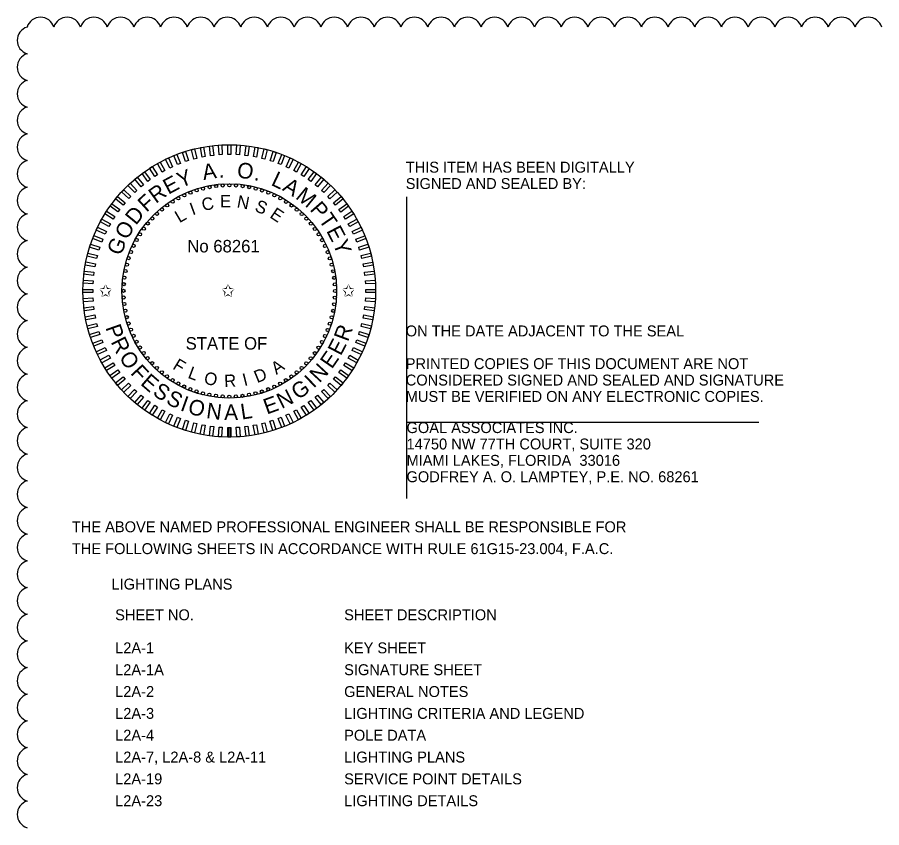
# Model space of a CAD drawing. Extents: x -811 to 10319, y -2309 to 9962.
# Drawn here: x -810.85 to -805.31, y -2194.13 to -2188.94 of the extents above; entities that cross this region are included whole.
import ezdxf

# ---------------------------------------------------------------- set-up
doc = ezdxf.new("R2010")
doc.units = 0
for name, color, linetype in [('AdhocPoint_dp', 7, 'Continuous'), ('PlotBorder_dp', 7, 'Continuous'), ('TextMinor', 7, 'Continuous'), ('TextMisc', 7, 'Continuous'), ('TextShtNo', 7, 'Continuous'), ('TextTitle', 7, 'Continuous')]:
    doc.layers.add(name, color=color, linetype=linetype)

msp = doc.modelspace()

# ---------------------------------------------------------------- linework, layer by layer
at = {"layer": 'AdhocPoint_dp'}
for p, q in [((-808.3546, -2190.0892), (-808.3546, -2192.0239)), ((-808.3546, -2191.5339), (-806.0979, -2191.5339))]:
    msp.add_line(p, q, dxfattribs=at)
at = {"layer": 'TextMinor'}
for radius in [0.9375, 0.6875]:
    msp.add_circle((-809.4901, -2190.6926), radius, dxfattribs=at)
at = {"layer": 'TextShtNo'}
for p, q in [((-809.5001, -2191.6301), (-809.5003, -2191.5676)), ((-809.4901, -2191.6301), (-809.4903, -2191.5676)), ((-809.4801, -2191.6301), (-809.4803, -2191.5676))]:
    msp.add_line(p, q, dxfattribs=at)
for points in [[(-809.5897, -2189.8232), (-809.6097, -2189.8257), (-809.6175, -2189.7638), (-809.5975, -2189.7612)], [(-809.5349, -2189.8187), (-809.555, -2189.8199), (-809.559, -2189.7576), (-809.5388, -2189.7563)], [(-809.4799, -2189.8176), (-809.5001, -2189.8176), (-809.5001, -2189.7551), (-809.4799, -2189.7551)], [(-809.425, -2189.8199), (-809.4452, -2189.8187), (-809.4412, -2189.7563), (-809.4211, -2189.7576)], [(-809.3703, -2189.8257), (-809.3904, -2189.8232), (-809.3825, -2189.7613), (-809.3625, -2189.7638)], [(-809.8028, -2189.8753), (-809.8215, -2189.8827), (-809.8445, -2189.8246), (-809.8258, -2189.8172)], [(-809.7508, -2189.8572), (-809.77, -2189.8635), (-809.7893, -2189.8041), (-809.7701, -2189.7979)], [(-809.6979, -2189.8425), (-809.7174, -2189.8475), (-809.7329, -2189.7871), (-809.7134, -2189.782)], [(-809.6441, -2189.8312), (-809.6639, -2189.8349), (-809.6756, -2189.7736), (-809.6558, -2189.7698)], [(-809.3162, -2189.835), (-809.336, -2189.8312), (-809.3243, -2189.7699), (-809.3045, -2189.7736)], [(-809.2626, -2189.8476), (-809.2822, -2189.8426), (-809.2667, -2189.7821), (-809.2471, -2189.7871)], [(-809.21, -2189.8635), (-809.2292, -2189.8573), (-809.2099, -2189.7979), (-809.1907, -2189.8042)], [(-809.1585, -2189.8828), (-809.1773, -2189.8753), (-809.1543, -2189.8173), (-809.1355, -2189.8247)], [(-809.9027, -2189.9209), (-809.9204, -2189.9306), (-809.9505, -2189.8759), (-809.9328, -2189.8662)], [(-809.8535, -2189.8965), (-809.8717, -2189.9051), (-809.8983, -2189.8486), (-809.8801, -2189.84)], [(-809.1083, -2189.9052), (-809.1266, -2189.8966), (-809.1, -2189.8401), (-809.0817, -2189.8487)], [(-809.0596, -2189.9307), (-809.0773, -2189.921), (-809.0473, -2189.8663), (-809.0296, -2189.876)], [(-809.9962, -2189.9787), (-810.0125, -2189.9906), (-810.0492, -2189.94), (-810.0329, -2189.9282)], [(-809.9504, -2189.9483), (-809.9674, -2189.9591), (-810.0009, -2189.9064), (-809.9838, -2189.8956)], [(-809.0127, -2189.9592), (-809.0297, -2189.9484), (-808.9962, -2189.8957), (-808.9792, -2189.9065)], [(-808.9676, -2189.9907), (-808.9839, -2189.9788), (-808.9472, -2189.9283), (-808.9308, -2189.9402)], [(-810.04, -2190.0119), (-810.0556, -2190.0247), (-810.0954, -2189.9766), (-810.0798, -2189.9638)], [(-808.9245, -2190.0249), (-808.9401, -2190.012), (-808.9003, -2189.9639), (-808.8847, -2189.9768)], [(-810.0817, -2190.0478), (-810.0964, -2190.0616), (-810.1392, -2190.0161), (-810.1244, -2190.0022)], [(-808.8837, -2190.0617), (-808.8984, -2190.0479), (-808.8557, -2190.0024), (-808.841, -2190.0162)], [(-810.1579, -2190.127), (-810.1707, -2190.1425), (-810.2188, -2190.1027), (-810.206, -2190.0872)], [(-810.121, -2190.0862), (-810.1348, -2190.1009), (-810.1804, -2190.0581), (-810.1665, -2190.0434)], [(-808.8453, -2190.101), (-808.8591, -2190.0863), (-808.8136, -2190.0436), (-808.7998, -2190.0583)], [(-808.8094, -2190.1427), (-808.8223, -2190.1271), (-808.7742, -2190.0873), (-808.7613, -2190.1029)], [(-810.192, -2190.17), (-810.2039, -2190.1864), (-810.2544, -2190.1497), (-810.2426, -2190.1333)], [(-808.7762, -2190.1865), (-808.7881, -2190.1702), (-808.7376, -2190.1335), (-808.7257, -2190.1498)], [(-810.2235, -2190.2151), (-810.2343, -2190.2322), (-810.287, -2190.1987), (-810.2762, -2190.1817)], [(-808.7459, -2190.2323), (-808.7567, -2190.2153), (-808.7039, -2190.1818), (-808.6931, -2190.1989)], [(-810.252, -2190.2621), (-810.2617, -2190.2798), (-810.3164, -2190.2497), (-810.3067, -2190.232)], [(-808.7184, -2190.28), (-808.7281, -2190.2623), (-808.6734, -2190.2322), (-808.6637, -2190.2499)], [(-810.2775, -2190.3108), (-810.2861, -2190.3291), (-810.3426, -2190.3025), (-810.334, -2190.2842)], [(-808.694, -2190.3292), (-808.7026, -2190.311), (-808.6461, -2190.2844), (-808.6375, -2190.3027)], [(-810.3, -2190.361), (-810.3074, -2190.3798), (-810.3654, -2190.3568), (-810.358, -2190.338)], [(-808.6728, -2190.3799), (-808.6802, -2190.3612), (-808.6222, -2190.3382), (-808.6147, -2190.357)], [(-810.3192, -2190.4125), (-810.3254, -2190.4317), (-810.3848, -2190.4124), (-810.3786, -2190.3932)], [(-808.6548, -2190.4319), (-808.661, -2190.4127), (-808.6016, -2190.3934), (-808.5954, -2190.4126)], [(-810.3351, -2190.4651), (-810.3401, -2190.4847), (-810.4006, -2190.4691), (-810.3956, -2190.4496)], [(-808.64, -2190.4849), (-808.6451, -2190.4653), (-808.5846, -2190.4498), (-808.5796, -2190.4693)], [(-810.3477, -2190.5186), (-810.3515, -2190.5385), (-810.4129, -2190.5268), (-810.4091, -2190.5069)], [(-808.6287, -2190.5386), (-808.6325, -2190.5188), (-808.5711, -2190.5071), (-808.5673, -2190.5269)], [(-810.357, -2190.5728), (-810.3595, -2190.5928), (-810.4215, -2190.585), (-810.4189, -2190.565)], [(-808.6207, -2190.593), (-808.6232, -2190.573), (-808.5613, -2190.5652), (-808.5588, -2190.5852)], [(-810.3628, -2190.6275), (-810.3641, -2190.6476), (-810.4264, -2190.6437), (-810.4251, -2190.6236)], [(-808.6162, -2190.6478), (-808.6174, -2190.6277), (-808.5551, -2190.6238), (-808.5539, -2190.6439)], [(-810.3652, -2190.6824), (-810.3652, -2190.7026), (-810.4276, -2190.7026), (-810.4276, -2190.6824)], [(-808.6151, -2190.7028), (-808.6151, -2190.6826), (-808.5527, -2190.6826), (-808.5527, -2190.7028)], [(-810.3641, -2190.7374), (-810.3628, -2190.7575), (-810.4251, -2190.7614), (-810.4264, -2190.7413)], [(-808.6175, -2190.7577), (-808.6162, -2190.7376), (-808.5539, -2190.7415), (-808.5551, -2190.7616)], [(-810.3595, -2190.7922), (-810.357, -2190.8122), (-810.4189, -2190.82), (-810.4215, -2190.8)], [(-808.6233, -2190.8124), (-808.6207, -2190.7923), (-808.5588, -2190.8002), (-808.5613, -2190.8202)], [(-810.3516, -2190.8466), (-810.3478, -2190.8664), (-810.4091, -2190.8781), (-810.4129, -2190.8583)], [(-808.6325, -2190.8666), (-808.6287, -2190.8467), (-808.5674, -2190.8584), (-808.5712, -2190.8783)], [(-810.3402, -2190.9003), (-810.3352, -2190.9199), (-810.3957, -2190.9354), (-810.4007, -2190.9159)], [(-808.6451, -2190.9201), (-808.6401, -2190.9005), (-808.5796, -2190.916), (-808.5846, -2190.9356)], [(-810.3255, -2190.9533), (-810.3192, -2190.9725), (-810.3786, -2190.9918), (-810.3849, -2190.9726)], [(-808.6611, -2190.9727), (-808.6548, -2190.9535), (-808.5954, -2190.9728), (-808.6017, -2190.992)], [(-810.3075, -2191.0052), (-810.3, -2191.024), (-810.3581, -2191.047), (-810.3655, -2191.0282)], [(-808.6803, -2191.0242), (-808.6729, -2191.0054), (-808.6148, -2191.0284), (-808.6222, -2191.0472)], [(-810.2862, -2191.0559), (-810.2776, -2191.0742), (-810.3341, -2191.1008), (-810.3427, -2191.0825)], [(-808.7027, -2191.0744), (-808.6941, -2191.0561), (-808.6376, -2191.0827), (-808.6462, -2191.101)], [(-810.2618, -2191.1052), (-810.2521, -2191.1229), (-810.3068, -2191.153), (-810.3165, -2191.1353)], [(-808.7282, -2191.1231), (-808.7185, -2191.1054), (-808.6638, -2191.1355), (-808.6735, -2191.1532)], [(-810.2344, -2191.1529), (-810.2236, -2191.1699), (-810.2763, -2191.2034), (-810.2871, -2191.1863)], [(-810.204, -2191.1987), (-810.1922, -2191.215), (-810.2427, -2191.2517), (-810.2545, -2191.2354)], [(-808.7882, -2191.2152), (-808.7763, -2191.1988), (-808.7258, -2191.2355), (-808.7377, -2191.2519)], [(-808.7568, -2191.1701), (-808.746, -2191.153), (-808.6932, -2191.1865), (-808.704, -2191.2035)], [(-810.1708, -2191.2425), (-810.158, -2191.2581), (-810.2061, -2191.2979), (-810.2189, -2191.2823)], [(-808.8224, -2191.2582), (-808.8095, -2191.2427), (-808.7614, -2191.2825), (-808.7743, -2191.298)], [(-810.135, -2191.2842), (-810.1211, -2191.2989), (-810.1667, -2191.3416), (-810.1805, -2191.3269)], [(-808.8592, -2191.299), (-808.8454, -2191.2843), (-808.7999, -2191.327), (-808.8137, -2191.3418)], [(-810.0965, -2191.3235), (-810.0818, -2191.3373), (-810.1246, -2191.3828), (-810.1393, -2191.369)], [(-810.0557, -2191.3603), (-810.0402, -2191.3732), (-810.08, -2191.4213), (-810.0955, -2191.4084)], [(-808.9402, -2191.3733), (-808.9247, -2191.3604), (-808.8848, -2191.4086), (-808.9004, -2191.4214)], [(-808.8985, -2191.3374), (-808.8838, -2191.3236), (-808.8411, -2191.3691), (-808.8558, -2191.383)], [(-810.0127, -2191.3945), (-809.9964, -2191.4064), (-810.0331, -2191.4569), (-810.0494, -2191.445)], [(-808.984, -2191.4065), (-808.9677, -2191.3946), (-808.931, -2191.4451), (-808.9473, -2191.457)], [(-809.9676, -2191.426), (-809.9505, -2191.4368), (-809.984, -2191.4895), (-810.001, -2191.4787)], [(-809.9206, -2191.4545), (-809.9029, -2191.4642), (-809.933, -2191.5189), (-809.9507, -2191.5092)], [(-809.0775, -2191.4643), (-809.0598, -2191.4546), (-809.0297, -2191.5093), (-809.0474, -2191.519)], [(-809.0299, -2191.4369), (-809.0128, -2191.4261), (-808.9794, -2191.4788), (-808.9964, -2191.4896)], [(-809.8719, -2191.48), (-809.8536, -2191.4886), (-809.8802, -2191.5451), (-809.8985, -2191.5365)], [(-809.8217, -2191.5024), (-809.8029, -2191.5099), (-809.8259, -2191.5679), (-809.8447, -2191.5605)], [(-809.7702, -2191.5217), (-809.751, -2191.5279), (-809.7703, -2191.5873), (-809.7895, -2191.581)], [(-809.2294, -2191.5279), (-809.2102, -2191.5217), (-809.1909, -2191.5811), (-809.2101, -2191.5873)], [(-809.1775, -2191.5099), (-809.1587, -2191.5025), (-809.1357, -2191.5606), (-809.1545, -2191.568)], [(-809.1268, -2191.4887), (-809.1085, -2191.4801), (-809.0819, -2191.5366), (-809.1002, -2191.5452)], [(-809.7176, -2191.5376), (-809.698, -2191.5426), (-809.7136, -2191.6031), (-809.7331, -2191.5981)], [(-809.6641, -2191.5502), (-809.6443, -2191.554), (-809.656, -2191.6153), (-809.6758, -2191.6116)], [(-809.6099, -2191.5594), (-809.5899, -2191.562), (-809.5977, -2191.6239), (-809.6177, -2191.6214)], [(-809.5552, -2191.5653), (-809.5351, -2191.5665), (-809.539, -2191.6288), (-809.5592, -2191.6276)], [(-809.5003, -2191.5676), (-809.4801, -2191.5676), (-809.4801, -2191.6301), (-809.5003, -2191.6301)], [(-809.4453, -2191.5665), (-809.4252, -2191.5653), (-809.4213, -2191.6276), (-809.4414, -2191.6289)], [(-809.3906, -2191.562), (-809.3705, -2191.5595), (-809.3627, -2191.6214), (-809.3827, -2191.624)], [(-809.3362, -2191.554), (-809.3163, -2191.5503), (-809.3046, -2191.6116), (-809.3245, -2191.6154)], [(-809.2824, -2191.5427), (-809.2628, -2191.5376), (-809.2473, -2191.5981), (-809.2668, -2191.6031)]]:
    msp.add_lwpolyline(points, close=True, dxfattribs=at)
for centre in [(-809.6989, -2190.0481), (-809.6581, -2190.0363), (-809.6165, -2190.027), (-809.5745, -2190.0204), (-809.5321, -2190.0164), (-809.4896, -2190.0151), (-809.447, -2190.0165), (-809.4047, -2190.0205), (-809.3626, -2190.0272), (-809.3211, -2190.0366), (-809.2802, -2190.0485), (-809.816, -2190.0987), (-809.7781, -2190.0794), (-809.739, -2190.0625), (-809.2402, -2190.0629), (-809.2012, -2190.0798), (-809.1633, -2190.0992), (-809.8879, -2190.1442), (-809.8527, -2190.1203), (-809.1266, -2190.1209), (-809.0915, -2190.1448), (-809.9535, -2190.1984), (-809.9215, -2190.1702), (-809.0579, -2190.171), (-809.026, -2190.1991), (-810.0118, -2190.2603), (-809.9836, -2190.2284), (-808.9959, -2190.2292), (-808.9678, -2190.2612), (-810.0379, -2190.2939), (-808.9417, -2190.2948), (-810.0835, -2190.3657), (-810.0618, -2190.3291), (-808.9178, -2190.3301), (-808.8962, -2190.3667), (-810.1029, -2190.4036), (-808.8769, -2190.4047), (-810.1343, -2190.4827), (-810.1198, -2190.4427), (-808.86, -2190.4437), (-808.8456, -2190.4838), (-810.1462, -2190.5236), (-808.8338, -2190.5247), (-810.1555, -2190.5651), (-808.8245, -2190.5662), (-810.1662, -2190.6495), (-810.1622, -2190.6071), (-808.8179, -2190.6082), (-808.814, -2190.6506), (-810.1676, -2190.692), (-808.8127, -2190.6932), (-810.1663, -2190.7346), (-808.814, -2190.7357), (-810.1623, -2190.7769), (-810.1557, -2190.819), (-808.8248, -2190.8201), (-808.8181, -2190.7781), (-810.1464, -2190.8605), (-808.8341, -2190.8616), (-810.1346, -2190.9014), (-808.846, -2190.9025), (-810.1202, -2190.9415), (-810.1034, -2190.9805), (-808.8774, -2190.9816), (-808.8604, -2190.9425), (-810.0841, -2191.0185), (-808.8967, -2191.0195), (-810.0624, -2191.0551), (-810.0385, -2191.0903), (-808.9424, -2191.0913), (-808.9184, -2191.0561), (-810.0125, -2191.124), (-809.9844, -2191.1559), (-808.9967, -2191.1568), (-808.9685, -2191.1249), (-809.9543, -2191.1861), (-809.0268, -2191.1868), (-809.9224, -2191.2142), (-809.8888, -2191.2403), (-809.8536, -2191.2643), (-809.1276, -2191.2649), (-809.0924, -2191.241), (-809.0587, -2191.215), (-809.817, -2191.286), (-809.7791, -2191.3053), (-809.74, -2191.3223), (-809.2413, -2191.3227), (-809.2022, -2191.3058), (-809.1642, -2191.2865), (-809.7, -2191.3367), (-809.6591, -2191.3486), (-809.6176, -2191.358), (-809.5756, -2191.3647), (-809.5332, -2191.3687), (-809.4901, -2191.3701), (-809.4481, -2191.3688), (-809.4058, -2191.3648), (-809.3637, -2191.3582), (-809.3222, -2191.3489), (-809.2813, -2191.3371)]:
    msp.add_circle(centre, 0.01, dxfattribs=at)
at = {"layer": 'TextTitle'}
for centre, start, end in [((-810.7002, -2189.0276), 17.5, 162.5), ((-810.5291, -2189.0276), 17.5, 162.5), ((-810.358, -2189.0276), 17.5, 162.5), ((-810.1868, -2189.0276), 17.5, 162.5), ((-810.0157, -2189.0276), 17.5, 162.5), ((-809.8446, -2189.0276), 17.5, 162.5), ((-809.6735, -2189.0276), 17.5, 162.5), ((-809.5024, -2189.0276), 17.5, 162.5), ((-809.3312, -2189.0276), 17.5, 162.5), ((-809.1601, -2189.0276), 17.5, 162.5), ((-808.989, -2189.0276), 17.5, 162.5), ((-808.8179, -2189.0276), 17.5, 162.5), ((-808.6467, -2189.0276), 17.5, 162.5), ((-808.4756, -2189.0276), 17.5, 162.5), ((-808.3045, -2189.0276), 17.5, 162.5), ((-808.1334, -2189.0276), 17.5, 162.5), ((-807.9622, -2189.0276), 17.5, 162.5), ((-807.7911, -2189.0276), 17.5, 162.5), ((-807.62, -2189.0276), 17.5, 162.5), ((-807.4489, -2189.0276), 17.5, 162.5), ((-807.2778, -2189.0276), 17.5, 162.5), ((-807.1066, -2189.0276), 17.5, 162.5), ((-806.9355, -2189.0276), 17.5, 162.5), ((-806.7644, -2189.0276), 17.5, 162.5), ((-806.5933, -2189.0276), 17.5, 162.5), ((-806.4221, -2189.0276), 17.5, 162.5), ((-806.251, -2189.0276), 17.5, 162.5), ((-806.0799, -2189.0276), 17.5, 162.5), ((-805.9088, -2189.0276), 17.5, 162.5), ((-805.7377, -2189.0276), 17.5, 162.5), ((-805.5665, -2189.0276), 17.5, 162.5), ((-805.3954, -2189.0276), 17.5, 162.5), ((-810.7588, -2189.0862), 107.5, 252.5), ((-810.7588, -2189.2573), 107.5, 252.5), ((-810.7588, -2189.4284), 107.5, 252.5), ((-810.7588, -2189.5996), 107.5, 252.5), ((-810.7588, -2189.7707), 107.5, 252.5), ((-810.7588, -2189.9418), 107.5, 252.5), ((-810.7588, -2190.1129), 107.5, 252.5), ((-810.7588, -2190.2841), 107.5, 252.5), ((-810.7588, -2190.4552), 107.5, 252.5), ((-810.7588, -2190.6263), 107.5, 252.5), ((-810.7588, -2190.7974), 107.5, 252.5), ((-810.7588, -2190.9685), 107.5, 252.5), ((-810.7588, -2191.1397), 107.5, 252.5), ((-810.7588, -2191.3108), 107.5, 252.5), ((-810.7588, -2191.4819), 107.5, 252.5), ((-810.7588, -2191.653), 107.5, 252.5), ((-810.7588, -2191.8242), 107.5, 252.5), ((-810.7588, -2191.9953), 107.5, 252.5), ((-810.7588, -2192.1664), 107.5, 252.5), ((-810.7588, -2192.3375), 107.5, 252.5), ((-810.7588, -2192.5087), 107.5, 252.5), ((-810.7588, -2192.6798), 107.5, 252.5), ((-810.7588, -2192.8509), 107.5, 252.5), ((-810.7588, -2193.022), 107.5, 252.5), ((-810.7588, -2193.1931), 107.5, 252.5), ((-810.7588, -2193.3643), 107.5, 252.5), ((-810.7588, -2193.5354), 107.5, 252.5), ((-810.7588, -2193.7065), 107.5, 252.5), ((-810.7588, -2193.8776), 107.5, 252.5), ((-810.7588, -2194.0488), 107.5, 252.5)]:
    msp.add_arc(centre, 0.0897, start, end, dxfattribs=at)

# ---------------------------------------------------------------- texts
at = {"layer": 'PlotBorder_dp'}
for s, p in [('THIS ITEM HAS BEEN DIGITALLY', (-808.3596, -2189.934)), ('SIGNED AND SEALED BY:', (-808.3596, -2190.039)), ('ON THE DATE ADJACENT TO THE SEAL', (-808.3596, -2190.984)), ('PRINTED COPIES OF THIS DOCUMENT ARE NOT ', (-808.3596, -2191.194)), ('CONSIDERED SIGNED AND SEALED AND SIGNATURE ', (-808.3596, -2191.299)), ('MUST BE VERIFIED ON ANY ELECTRONIC COPIES.', (-808.3596, -2191.404)), ('GOAL ASSOCIATES INC.', (-808.3546, -2191.6039)), ('14750 NW 77TH COURT, SUITE 320', (-808.3546, -2191.7089)), ('MIAMI LAKES, FLORIDA  33016', (-808.3546, -2191.8139)), ('GODFREY A. O. LAMPTEY, P.E. NO. 68261', (-808.3546, -2191.9189)), ('THE ABOVE NAMED PROFESSIONAL ENGINEER SHALL BE RESPONSIBLE FOR ', (-810.4987, -2192.24)), ('THE FOLLOWING SHEETS IN ACCORDANCE WITH RULE 61G15-23.004, F.A.C.', (-810.4987, -2192.38)), ('LIGHTING PLANS', (-810.245, -2192.6071))]:
    msp.add_text(s, height=0.07, dxfattribs=at).set_placement(p)
at = {"layer": 'TextMisc'}
for s, p in [('SHEET NO.', (-810.2215, -2192.8041)), ('SHEET DESCRIPTION', (-808.7542, -2192.8041)), ('L2A-1', (-810.2215, -2193.0162)), ('KEY SHEET', (-808.7542, -2193.0162)), ('L2A-1A', (-810.2215, -2193.1562)), ('SIGNATURE SHEET', (-808.7542, -2193.1562)), ('L2A-2', (-810.2215, -2193.2962)), ('GENERAL NOTES', (-808.7542, -2193.2962)), ('L2A-3', (-810.2215, -2193.4362)), ('LIGHTING CRITERIA AND LEGEND', (-808.7542, -2193.4362)), ('L2A-4 ', (-810.2215, -2193.5762)), ('POLE DATA', (-808.7542, -2193.5762)), ('L2A-7, L2A-8 & L2A-11', (-810.2215, -2193.7162)), ('LIGHTING PLANS', (-808.7542, -2193.7162)), ('L2A-19', (-810.2215, -2193.8562)), ('SERVICE POINT DETAILS', (-808.7542, -2193.8562)), ('L2A-23', (-810.2215, -2193.9962)), ('LIGHTING DETAILS', (-808.7542, -2193.9962))]:
    msp.add_text(s, height=0.07, dxfattribs=at).set_placement(p)
at = {"layer": 'TextShtNo'}
for s, height, rotation, p in [('O', 0.1, 352.1877, (-809.4449, -2189.9645)), ('Y', 0.1, 21.0633, (-809.8021, -2190.0332)), ('A', 0.1, 8.8088, (-809.6551, -2189.982)), ('L', 0.1, 334.6727, (-809.2279, -2190.0118)), ('E', 0.1, 28.1055, (-809.8806, -2190.0764)), ('.', 0.1, 1.0418, (-809.5575, -2189.9662)), ('.', 0.1, 343.5268, (-809.3358, -2189.9796)), ('A', 0.1, 328.4096, (-809.1552, -2190.0445)), ('R', 0.1, 35.9269, (-809.9609, -2190.1353)), ('M', 0.1, 320.6426, (-809.0707, -2190.0957)), ('F', 0.1, 42.3772, (-810.0205, -2190.1917)), ('C', 0.08, 12.2025, (-809.6579, -2190.181)), ('E', 0.08, 0.4186, (-809.5498, -2190.1575)), ('N', 0.08, 349.2914, (-809.4455, -2190.1561)), ('I', 0.08, 20.0117, (-809.7258, -2190.2085)), ('S', 0.08, 337.0221, (-809.3325, -2190.1778)), ('P', 0.1, 311.1966, (-808.9784, -2190.1727)), ('D', 0.1, 50.8569, (-810.0886, -2190.2754)), ('L', 0.08, 30.4021, (-809.8093, -2190.259)), ('E', 0.08, 325.8663, (-809.2358, -2190.218)), ('T', 0.1, 304.4563, (-808.9209, -2190.2363)), ('O', 0.1, 59.5178, (-810.1446, -2190.3702)), ('E', 0.1, 297.6315, (-808.8707, -2190.3072)), ('G', 0.1, 68.0518, (-810.1851, -2190.4709)), ('Y', 0.1, 290.5893, (-808.8281, -2190.386)), ('P', 0.1, 289.4055, (-810.2848, -2190.9272)), ('R', 0.1, 69.5134, (-808.7299, -2191.0223)), ('R', 0.1, 296.1458, (-810.2518, -2191.0188)), ('E', 0.1, 62.4712, (-808.7761, -2191.113)), ('O', 0.1, 303.9671, (-810.2003, -2191.1194)), ('E', 0.1, 55.4289, (-808.833, -2191.1974)), ('F', 0.08, 328.7241, (-809.8582, -2191.1892)), ('A', 0.08, 34.4992, (-809.1883, -2191.232)), ('F', 0.1, 312.628, (-810.1279, -2191.2215)), ('L', 0.08, 339.2916, (-809.7609, -2191.2483)), ('D', 0.08, 22.0128, (-809.312, -2191.2845)), ('N', 0.1, 47.1788, (-808.9123, -2191.2864)), ('E', 0.1, 319.0783, (-810.0645, -2191.2898)), ('O', 0.08, 349.6821, (-809.6562, -2191.288)), ('R', 0.08, 2.3398, (-809.5217, -2191.3099)), ('I', 0.08, 14.2037, (-809.3941, -2191.3032)), ('I', 0.1, 43.6456, (-808.9499, -2191.3209)), ('S', 0.1, 326.1206, (-809.9869, -2191.3557)), ('G', 0.1, 35.1115, (-809.0492, -2191.3941)), ('S', 0.1, 333.193, (-809.9015, -2191.4119)), ('I', 0.1, 340.2654, (-809.8098, -2191.457)), ('E', 0.1, 19.8191, (-809.2498, -2191.4856)), ('N', 0.1, 26.8614, (-809.1544, -2191.4501)), ('O', 0.1, 343.7986, (-809.7621, -2191.4753)), ('N', 0.1, 352.4595, (-809.6411, -2191.5073)), ('A', 0.1, 0.7097, (-809.5227, -2191.5206)), ('L', 0.1, 8.4767, (-809.4105, -2191.5174))]:
    msp.add_text(s, height=height, rotation=rotation, dxfattribs=at).set_placement(p)
for s, p in [('No 68261', (-809.7591, -2190.4454)), ('✩', (-810.3251, -2190.7305)), ('✩', (-809.5404, -2190.7305)), ('✩', (-808.7685, -2190.7305)), ('STATE OF', (-809.7698, -2191.0688))]:
    msp.add_text(s, height=0.08, dxfattribs=at).set_placement(p)

doc.saveas('drawing.dxf')
